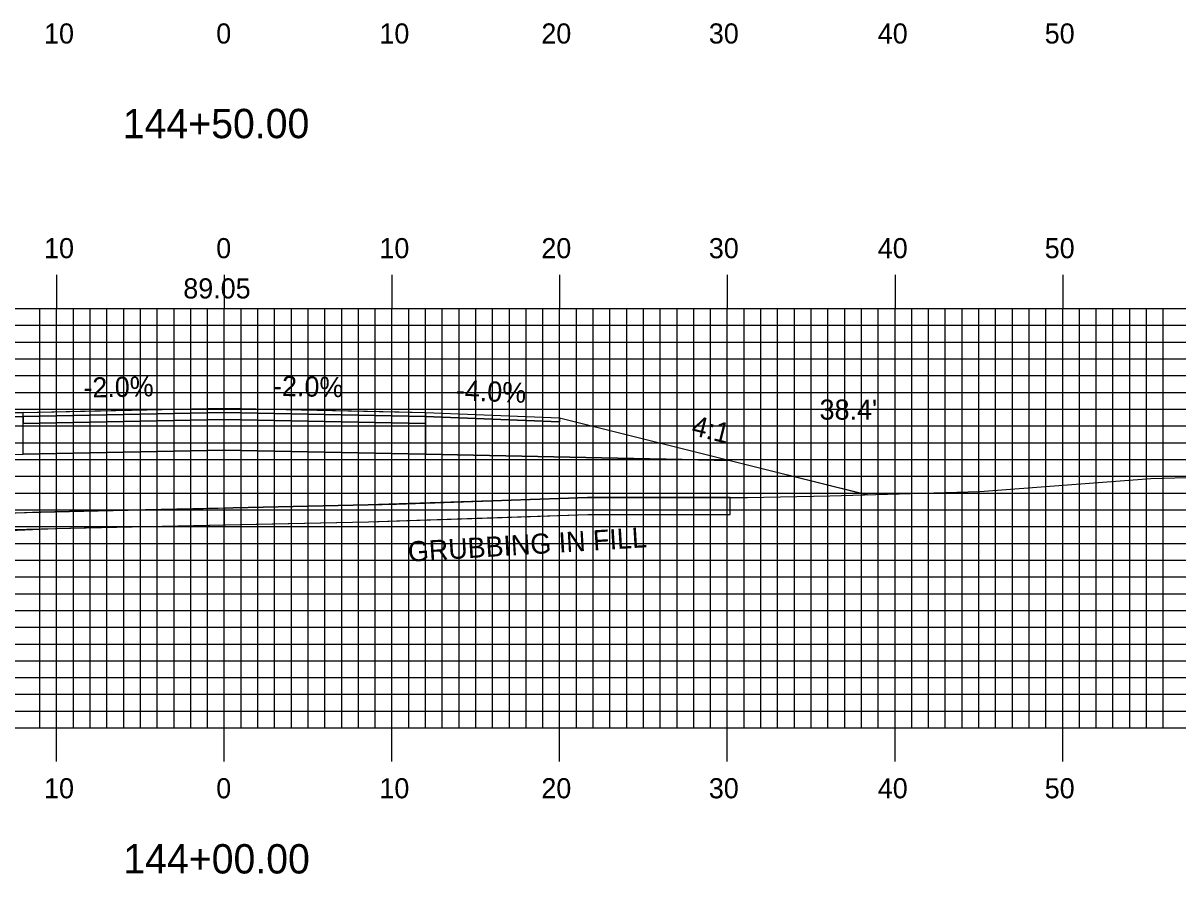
# Model space of a CAD drawing. Extents: x 1777138 to 1777481, y 442591 to 442811.
# Drawn here: x 1777291.8 to 1777360.6, y 442700 to 442750.7 of the extents above; entities that cross this region are included whole.
import ezdxf

# ---------------------------------------------------------------- set-up
doc = ezdxf.new("R2010")
doc.units = 0
for name, color, linetype in [('ANNOTATION', 7, 'Continuous'), ('D_Roadway_Centerline', 7, 'Continuous'), ('D_Roadway_Centerline_Text', 7, 'Continuous'), ('D_Roadway_Edge_Shoulder', 7, 'Continuous'), ('D_Roadway_Edge_TW', 7, 'Continuous'), ('D_Roadway_Pavement', 7, 'Continuous'), ('D_Roadway_SlopeLines', 7, 'Continuous'), ('D_Roadway_SubGrade', 7, 'Continuous'), ('D_Text_Standard', 7, 'Continuous'), ('GRUBBING IN FILL', 7, 'Continuous'), ('H_V ANNOTATION', 7, 'Continuous'), ('MAJOR', 7, 'Continuous'), ('MINOR', 7, 'Continuous'), ('S_Roadway_Centerline', 7, 'Continuous')]:
    doc.layers.add(name, color=color, linetype=linetype)

msp = doc.modelspace()

# ---------------------------------------------------------------- linework, layer by layer
at = {"layer": 'D_Roadway_Centerline'}
msp.add_lwpolyline([(1777256.927, 442719.091), (1777257.055, 442719.134), (1777263.521, 442721.289), (1777273.477, 442724.608), (1777273.487, 442724.611), (1777279.919, 442726.755), (1777280.753, 442727.033), (1777280.764, 442727.037), (1777281.762, 442727.077), (1777283.763, 442727.157), (1777291.763, 442727.477), (1777291.764, 442727.477), (1777291.765, 442727.477), (1777296.036, 442727.563), (1777303.764, 442727.717), (1777314.183, 442727.509), (1777315.763, 442727.477), (1777323.763, 442727.157), (1777333.938, 442724.613), (1777335.764, 442724.157), (1777342.078, 442722.579), (1777342.131, 442722.565)], dxfattribs=at)
at = {"layer": 'D_Roadway_Edge_Shoulder'}
for points in [[(1777291.764, 442727.477), (1777283.763, 442727.157), (1777283.763, 442727.157), (1777280.764, 442727.037), (1777280.764, 442726.787), (1777291.764, 442727.227)], [(1777315.763, 442727.477), (1777323.763, 442727.157), (1777323.763, 442726.907), (1777315.763, 442727.227)]]:
    msp.add_lwpolyline(points, close=True, dxfattribs=at)
at = {"layer": 'D_Roadway_Edge_TW'}
msp.add_lwpolyline([(1777291.764, 442727.227), (1777291.764, 442727.477), (1777303.764, 442727.717), (1777315.763, 442727.477), (1777315.763, 442727.227), (1777303.764, 442727.467)], close=True, dxfattribs=at)
at = {"layer": 'D_Roadway_Pavement'}
msp.add_lwpolyline([(1777291.764, 442726.81), (1777291.764, 442727.227), (1777303.764, 442727.467), (1777315.763, 442727.227), (1777315.763, 442726.81), (1777303.764, 442727.05)], close=True, dxfattribs=at)
for points in [[(1777291.764, 442727.227), (1777291.764, 442726.81)], [(1777315.763, 442727.227), (1777315.763, 442726.81)]]:
    msp.add_lwpolyline(points, dxfattribs=at)
at = {"layer": 'D_Roadway_SlopeLines'}
msp.add_lwpolyline([(1777323.763, 442727.157), (1777335.764, 442724.157), (1777342.131, 442722.565)], dxfattribs=at)
at = {"layer": 'D_Roadway_SubGrade'}
for points in [[(1777291.764, 442726.81), (1777291.764, 442727.227), (1777280.764, 442726.787), (1777280.764, 442727.037), (1777273.487, 442724.611), (1777291.764, 442724.977)], [(1777291.764, 442724.977), (1777291.764, 442727.227), (1777291.764, 442726.81), (1777303.764, 442727.05), (1777315.763, 442726.81), (1777315.763, 442727.227), (1777315.763, 442724.977), (1777303.764, 442725.217)], [(1777315.763, 442726.81), (1777315.763, 442727.227), (1777323.763, 442726.907), (1777323.763, 442727.157), (1777333.938, 442724.613), (1777315.763, 442724.977)]]:
    msp.add_lwpolyline(points, close=True, dxfattribs=at)
at = {"layer": 'GRUBBING IN FILL'}
for points in [[(1777273.487, 442724.611), (1777291.764, 442724.977), (1777303.764, 442725.217), (1777315.763, 442724.977), (1777333.938, 442724.613)], [(1777273.487, 442724.611), (1777291.764, 442724.977), (1777303.764, 442725.217), (1777315.763, 442724.977), (1777333.938, 442724.613)], [(1777273.487, 442719.582), (1777283.599, 442720.113), (1777290.553, 442720.465), (1777291.141, 442720.492), (1777296.258, 442720.608), (1777312.369, 442720.954), (1777314.061, 442721.004), (1777325.451, 442721.39), (1777333.938, 442721.391)], [(1777273.487, 442719.582), (1777283.599, 442720.113), (1777290.553, 442720.465), (1777291.141, 442720.492), (1777296.258, 442720.608), (1777312.369, 442720.954), (1777314.061, 442721.004), (1777325.451, 442721.39), (1777333.938, 442721.391)]]:
    msp.add_lwpolyline(points, dxfattribs=at)
for points in [[(1777303.764, 442720.769), (1777312.369, 442720.954), (1777319.756, 442721.197), (1777325.451, 442721.39), (1777329.694, 442721.39), (1777333.938, 442721.391), (1777333.938, 442722.391), (1777330.202, 442722.39), (1777325.434, 442722.39), (1777319.732, 442722.196), (1777312.344, 442721.953), (1777304.29, 442721.78), (1777303.764, 442721.769)], [(1777303.764, 442720.769), (1777312.369, 442720.954), (1777319.756, 442721.197), (1777325.451, 442721.39), (1777329.694, 442721.39), (1777333.938, 442721.391), (1777333.938, 442722.391), (1777330.202, 442722.39), (1777325.434, 442722.39), (1777319.732, 442722.196), (1777312.344, 442721.953), (1777304.29, 442721.78), (1777303.764, 442721.769)], [(1777273.487, 442719.582), (1777283.599, 442720.113), (1777293.699, 442720.55), (1777303.764, 442720.769), (1777303.764, 442721.769), (1777296.236, 442721.608), (1777292.808, 442721.534), (1777287.026, 442721.288), (1777275.174, 442720.672), (1777273.487, 442720.583)], [(1777273.487, 442719.582), (1777283.599, 442720.113), (1777293.699, 442720.55), (1777303.764, 442720.769), (1777303.764, 442721.769), (1777296.236, 442721.608), (1777292.808, 442721.534), (1777287.026, 442721.288), (1777275.174, 442720.672), (1777273.487, 442720.583)]]:
    msp.add_lwpolyline(points, close=True, dxfattribs=at)
at = {"layer": 'MAJOR'}
for p, q in [((1777293.764, 442735.669), (1777293.764, 442733.665)), ((1777303.764, 442735.669), (1777303.764, 442733.665)), ((1777313.764, 442735.669), (1777313.764, 442733.665)), ((1777323.764, 442735.669), (1777323.764, 442733.665)), ((1777333.764, 442735.669), (1777333.764, 442733.665)), ((1777343.764, 442735.669), (1777343.764, 442733.665)), ((1777353.764, 442735.669), (1777353.764, 442733.665)), ((1777163.764, 442733.665), (1777443.764, 442733.665)), ((1777163.764, 442733.665), (1777443.764, 442733.665)), ((1777293.764, 442708.665), (1777293.764, 442733.665)), ((1777303.764, 442708.665), (1777303.764, 442733.665)), ((1777313.764, 442708.665), (1777313.764, 442733.665)), ((1777323.764, 442708.665), (1777323.764, 442733.665)), ((1777333.764, 442708.665), (1777333.764, 442733.665)), ((1777343.764, 442708.665), (1777343.764, 442733.665)), ((1777353.764, 442708.665), (1777353.764, 442733.665)), ((1777163.764, 442728.665), (1777443.764, 442728.665)), ((1777163.764, 442723.665), (1777443.764, 442723.665)), ((1777163.764, 442718.665), (1777443.764, 442718.665)), ((1777163.764, 442713.665), (1777443.764, 442713.665)), ((1777163.764, 442708.665), (1777443.764, 442708.665)), ((1777163.764, 442708.665), (1777443.764, 442708.665)), ((1777293.764, 442706.661), (1777293.764, 442708.665)), ((1777303.764, 442706.661), (1777303.764, 442708.665)), ((1777313.764, 442706.661), (1777313.764, 442708.665)), ((1777323.764, 442706.661), (1777323.764, 442708.665)), ((1777333.764, 442706.661), (1777333.764, 442708.665)), ((1777343.764, 442706.661), (1777343.764, 442708.665)), ((1777353.764, 442706.661), (1777353.764, 442708.665))]:
    msp.add_line(p, q, dxfattribs=at)
at = {"layer": 'MINOR'}
for p, q in [((1777292.764, 442708.665), (1777292.764, 442733.665)), ((1777294.764, 442708.665), (1777294.764, 442733.665)), ((1777295.764, 442708.665), (1777295.764, 442733.665)), ((1777296.764, 442708.665), (1777296.764, 442733.665)), ((1777297.764, 442708.665), (1777297.764, 442733.665)), ((1777298.764, 442708.665), (1777298.764, 442733.665)), ((1777299.764, 442708.665), (1777299.764, 442733.665)), ((1777300.764, 442708.665), (1777300.764, 442733.665)), ((1777301.764, 442708.665), (1777301.764, 442733.665)), ((1777302.764, 442708.665), (1777302.764, 442733.665)), ((1777304.764, 442708.665), (1777304.764, 442733.665)), ((1777305.764, 442708.665), (1777305.764, 442733.665)), ((1777306.764, 442708.665), (1777306.764, 442733.665)), ((1777307.764, 442708.665), (1777307.764, 442733.665)), ((1777308.764, 442708.665), (1777308.764, 442733.665)), ((1777309.764, 442708.665), (1777309.764, 442733.665)), ((1777310.764, 442708.665), (1777310.764, 442733.665)), ((1777311.764, 442708.665), (1777311.764, 442733.665)), ((1777312.764, 442708.665), (1777312.764, 442733.665)), ((1777314.764, 442708.665), (1777314.764, 442733.665)), ((1777315.764, 442708.665), (1777315.764, 442733.665)), ((1777316.764, 442708.665), (1777316.764, 442733.665)), ((1777317.764, 442708.665), (1777317.764, 442733.665)), ((1777318.764, 442708.665), (1777318.764, 442733.665)), ((1777319.764, 442708.665), (1777319.764, 442733.665)), ((1777320.764, 442708.665), (1777320.764, 442733.665)), ((1777321.764, 442708.665), (1777321.764, 442733.665)), ((1777322.764, 442708.665), (1777322.764, 442733.665)), ((1777324.764, 442708.665), (1777324.764, 442733.665)), ((1777325.764, 442708.665), (1777325.764, 442733.665)), ((1777326.764, 442708.665), (1777326.764, 442733.665)), ((1777327.764, 442708.665), (1777327.764, 442733.665)), ((1777328.764, 442708.665), (1777328.764, 442733.665)), ((1777329.764, 442708.665), (1777329.764, 442733.665)), ((1777330.764, 442708.665), (1777330.764, 442733.665)), ((1777331.764, 442708.665), (1777331.764, 442733.665)), ((1777332.764, 442708.665), (1777332.764, 442733.665)), ((1777334.764, 442708.665), (1777334.764, 442733.665)), ((1777335.764, 442708.665), (1777335.764, 442733.665)), ((1777336.764, 442708.665), (1777336.764, 442733.665)), ((1777337.764, 442708.665), (1777337.764, 442733.665)), ((1777338.764, 442708.665), (1777338.764, 442733.665)), ((1777339.764, 442708.665), (1777339.764, 442733.665)), ((1777340.764, 442708.665), (1777340.764, 442733.665)), ((1777341.764, 442708.665), (1777341.764, 442733.665)), ((1777342.764, 442708.665), (1777342.764, 442733.665)), ((1777344.764, 442708.665), (1777344.764, 442733.665)), ((1777345.764, 442708.665), (1777345.764, 442733.665)), ((1777346.764, 442708.665), (1777346.764, 442733.665)), ((1777347.764, 442708.665), (1777347.764, 442733.665)), ((1777348.764, 442708.665), (1777348.764, 442733.665)), ((1777349.764, 442708.665), (1777349.764, 442733.665)), ((1777350.764, 442708.665), (1777350.764, 442733.665)), ((1777351.764, 442708.665), (1777351.764, 442733.665)), ((1777352.764, 442708.665), (1777352.764, 442733.665)), ((1777354.764, 442708.665), (1777354.764, 442733.665)), ((1777355.764, 442708.665), (1777355.764, 442733.665)), ((1777356.764, 442708.665), (1777356.764, 442733.665)), ((1777357.764, 442708.665), (1777357.764, 442733.665)), ((1777358.764, 442708.665), (1777358.764, 442733.665)), ((1777359.764, 442708.665), (1777359.764, 442733.665)), ((1777163.764, 442732.665), (1777443.764, 442732.665)), ((1777163.764, 442731.665), (1777443.764, 442731.665)), ((1777163.764, 442730.665), (1777443.764, 442730.665)), ((1777163.764, 442729.665), (1777443.764, 442729.665)), ((1777163.764, 442727.665), (1777443.764, 442727.665)), ((1777163.764, 442726.665), (1777443.764, 442726.665)), ((1777163.764, 442725.665), (1777443.764, 442725.665)), ((1777163.764, 442724.665), (1777443.764, 442724.665)), ((1777163.764, 442722.665), (1777443.764, 442722.665)), ((1777163.764, 442721.665), (1777443.764, 442721.665)), ((1777163.764, 442720.665), (1777443.764, 442720.665)), ((1777163.764, 442719.665), (1777443.764, 442719.665)), ((1777163.764, 442717.665), (1777443.764, 442717.665)), ((1777163.764, 442716.665), (1777443.764, 442716.665)), ((1777163.764, 442715.665), (1777443.764, 442715.665)), ((1777163.764, 442714.665), (1777443.764, 442714.665)), ((1777163.764, 442712.665), (1777443.764, 442712.665)), ((1777163.764, 442711.665), (1777443.764, 442711.665)), ((1777163.764, 442710.665), (1777443.764, 442710.665)), ((1777163.764, 442709.665), (1777443.764, 442709.665))]:
    msp.add_line(p, q, dxfattribs=at)
at = {"layer": 'S_Roadway_Centerline'}
msp.add_lwpolyline([(1777223.019, 442717.023), (1777242.609, 442717.933), (1777243.247, 442718), (1777255.107, 442718.877), (1777266.155, 442720.177), (1777266.801, 442720.232), (1777283.548, 442721.111), (1777290.505, 442721.464), (1777291.107, 442721.491), (1777296.236, 442721.608), (1777312.344, 442721.953), (1777314.029, 442722.003), (1777325.434, 442722.39), (1777334.971, 442722.391), (1777339.877, 442722.499), (1777348.822, 442722.761), (1777359.018, 442723.529), (1777361.897, 442723.609)], dxfattribs=at)

# ---------------------------------------------------------------- texts
at = {"layer": 'ANNOTATION'}
for s, rotation, p in [('-2.0%', 1.14575, (1777295.371, 442728.35)), ('-2.0%', 358.85418, (1777306.66, 442728.46)), ('-4.0%', 357.70947, (1777317.555, 442728.207)), ('4:1', 345.9618, (1777331.564, 442726.142))]:
    msp.add_text(s, height=1.2, rotation=rotation, dxfattribs=at).set_placement(p)
at = {"layer": 'D_Roadway_Centerline'}
for s, p in [('C', (1777303.759, 442727.717)), ('L', (1777303.764, 442727.71))]:
    msp.add_text(s, height=0.0146, dxfattribs=at).set_placement(p)
at = {"layer": 'D_Roadway_Centerline_Text'}
msp.add_text('89.05', height=1.2, dxfattribs=at).set_placement((1777301.318, 442734.266))
at = {"layer": 'D_Text_Standard'}
msp.add_text("38.4'", height=1.2, dxfattribs=at).set_placement((1777339.267, 442727.041))
at = {"layer": 'GRUBBING IN FILL'}
msp.add_text('GRUBBING IN FILL', height=1.2, rotation=3.49622, dxfattribs=at).set_placement((1777314.753, 442718.567))
at = {"layer": 'H_V ANNOTATION'}
for s, height, p in [('10', 1.2, (1777293.014, 442749.465)), ('0', 1.2, (1777303.282, 442749.465)), ('10', 1.2, (1777313.014, 442749.465)), ('20', 1.2, (1777322.672, 442749.465)), ('30', 1.2, (1777332.661, 442749.465)), ('40', 1.2, (1777342.736, 442749.465)), ('50', 1.2, (1777352.693, 442749.465)), ('144+50.00', 1.75, (1777297.709, 442743.821)), ('10', 1.2, (1777293.014, 442736.665)), ('0', 1.2, (1777303.282, 442736.665)), ('10', 1.2, (1777313.014, 442736.665)), ('20', 1.2, (1777322.672, 442736.665)), ('30', 1.2, (1777332.661, 442736.665)), ('40', 1.2, (1777342.736, 442736.665)), ('50', 1.2, (1777352.693, 442736.665)), ('10', 1.2, (1777293.014, 442704.465)), ('0', 1.2, (1777303.282, 442704.465)), ('10', 1.2, (1777313.014, 442704.465)), ('20', 1.2, (1777322.672, 442704.465)), ('30', 1.2, (1777332.661, 442704.465)), ('40', 1.2, (1777342.736, 442704.465)), ('50', 1.2, (1777352.693, 442704.465)), ('144+00.00', 1.75, (1777297.74, 442699.983))]:
    msp.add_text(s, height=height, dxfattribs=at).set_placement(p)

doc.saveas('drawing.dxf')
